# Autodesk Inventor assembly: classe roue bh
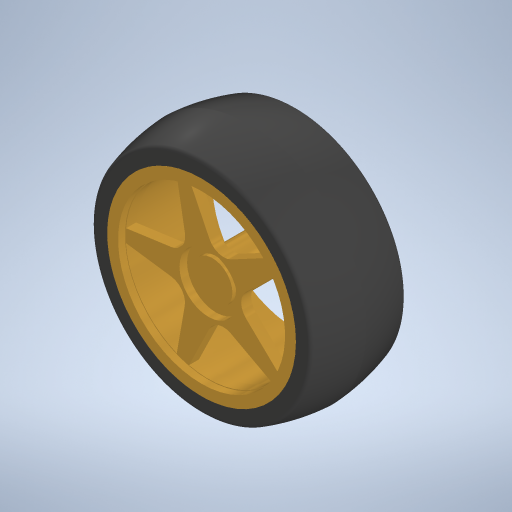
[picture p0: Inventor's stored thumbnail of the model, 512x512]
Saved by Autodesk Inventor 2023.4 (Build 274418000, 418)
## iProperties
Created: 2024-03
Part Number: classe roue bh
Document SubType Name: Assembly
Designer: mel
Author: mel
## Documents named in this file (3)
- D:\travail\année 2023-2024\IT\char à voile\classe roue bh.iam
- D:\travail\année 2023-2024\IT\char à voile\Voiture-Inventor\jante.ipt
- D:\travail\année 2023-2024\IT\char à voile\Voiture-Inventor\pneu.ipt
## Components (2 placed, 2 different names)
1. jante:1 — Logement:1
2. pneu:1 — Logement:1
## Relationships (1: Insert 1)
- Logement:1 [Insert]: jante:1 ↔ pneu:1
